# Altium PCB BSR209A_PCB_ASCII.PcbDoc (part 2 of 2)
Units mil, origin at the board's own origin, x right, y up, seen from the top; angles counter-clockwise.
Board outline 3820.03 x 2030.03 mil, 4 copper layers (Top Layer, MidLayer1, MidLayer2, Bottom Layer), stack 59.4 mil thick; 68 components, 18 nets, 122 pads, 73 vias.
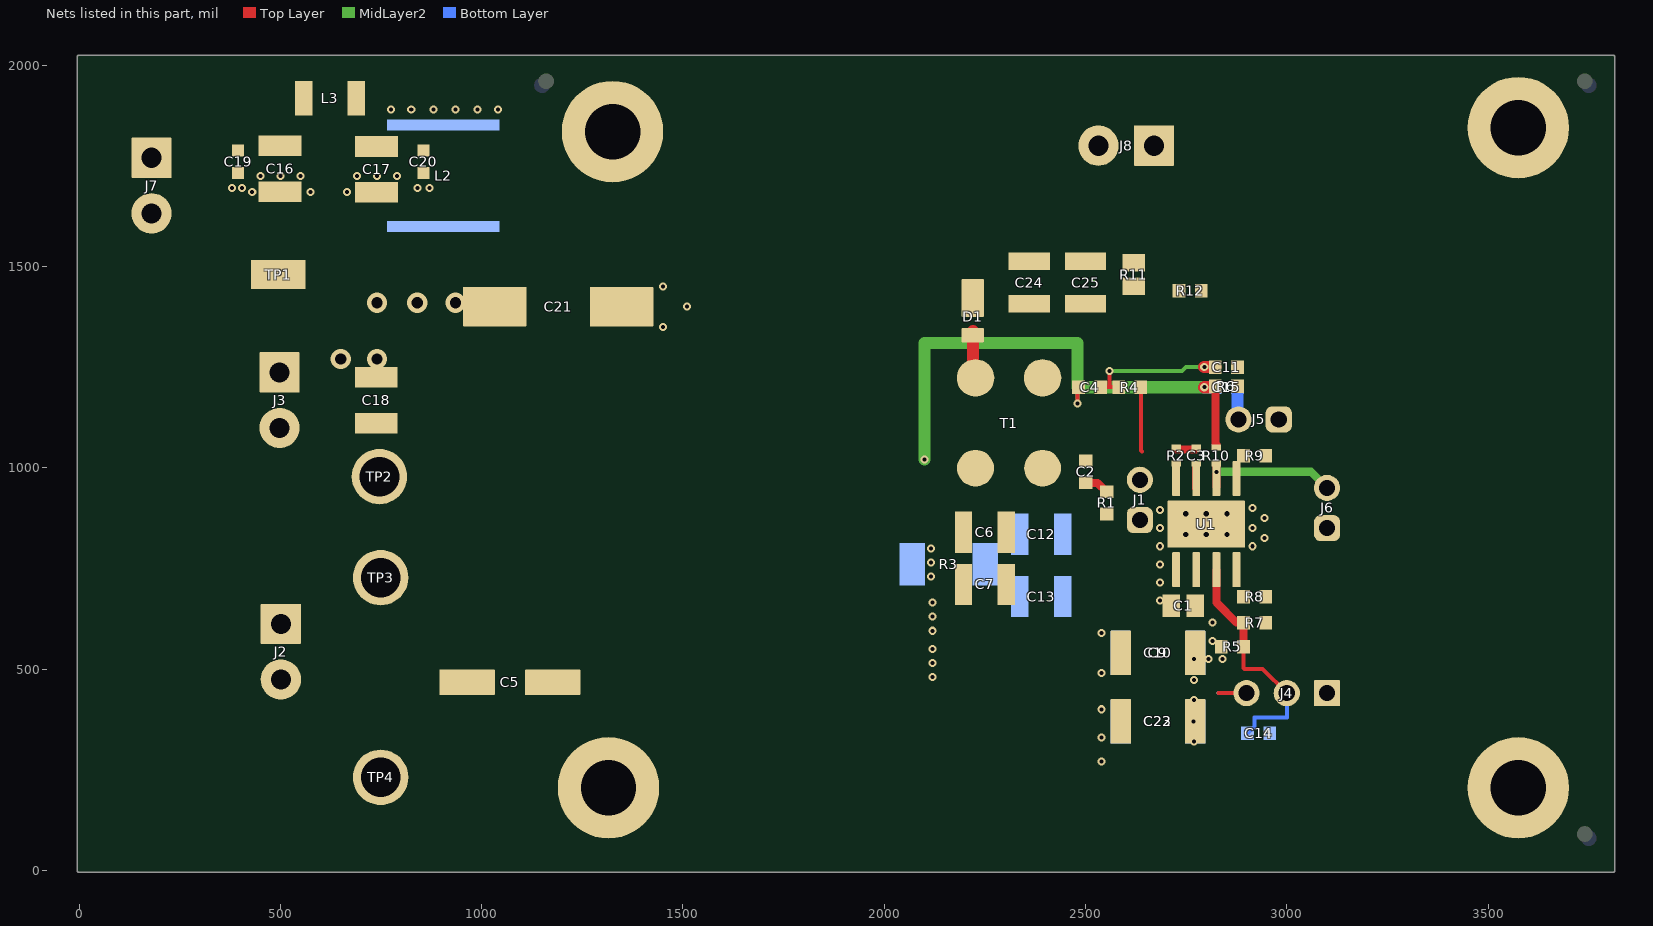
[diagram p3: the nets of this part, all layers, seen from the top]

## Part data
C1: library part CMP-0007897-1, "CAP, CERM, 0.1 uF, 250 V, +/- 10%, X7T, 0805"
C2: library part CMP-0081318-1, "CAP, CERM, 1000 pF, 200 V,+/- 10%, X7R, 0603"
C3: library part CMP-0006357-2, "CAP, CERM, 2200 pF, 50 V, +/- 10%, X7R, AEC-Q200 Grade 1, 0402"
C4: library part CMP-0007087-4, "CAP, CERM, 3300 pF, 100 V, +/- 10%, X7R, AEC-Q200 Grade 1, 0603"
C5: library part CMP-0081462-1, "CAP, AL, 100 µF, 25 V, +/- 20%, SMD"
C6 C7 C24 C25: library part CMP-0084059-1, "CAP, CERM, 22 µF, 25 V,+/- 10%, X5R, AEC-Q200 Grade 3, 1210"
C9 C10 C22 C23: library part CMP-0091301-1, "Cap Ceramic 1uF 250V X7T 10% Pad SMD 1812 +125°C Automotive T/R"
C11: library part CMP-0006952-4, "CAP, CERM, 56 pF, 50 V, +/- 5%, C0G/NP0, 0603"
C12 C13: library part CMP-0009255-2, "CAP, CERM, 22 uF, 25 V, +/- 10%, X7R, AEC-Q200 Grade 1, 1210"
C14: library part CMP-0080063-1, "CAP, CERM, 0.01 µF, 100 V,+/- 10%, X8R, AEC-Q200 Grade 0, 0603"
C15: library part CMP-0006844-4, "CAP, CERM, 1000 pF, 50 V, +/- 5%, X7R, AEC-Q200 Grade 1, 0603"
C16 C17 C18: library part CMP-0009150-2, "CAP, CERM, 4.7 uF, 100 V, +/- 10%, X7S, AEC-Q200 Grade 1, 1210"
C19 C20: library part CMP-0081011-1, "CAP, CERM, 0.1 µF, 100 V,+/- 10%, X7R, AEC-Q200 Grade 1, 0603"
C21: library part CMP-0091226-1, "Aluminum Electrolytic Capacitors Radial 33uF 20% 160V, Can - SMD - 2000 Hrs @ 125°C"
D1: library part CMP-0093179-1, "Rectifier Diode Schottky 200V 1A 2-Pin SOD-123HE T/R"
FID1 FID2 FID3 FID4 FID5 FID6: library part CMP-0077181-1, "Fiducial mark.  There is nothing to buy or mount."
J1 J5 J6: library part CMP-0075405-2, "Header, 100mil, 2x1, Gold, TH"
J2 J3 J7 J8: library part CMP-0074913-1, "Terminal Block, 3.5mm Pitch, 2x1, TH"
J4: library part CMP-0075484-1, "Header, 100mil, 3x1, Gold, TH"
L2: library part CMP-0061601-2, "Inductor, Shielded Drum Core, Ferrite, 15 uH, 1.8 A, 0.05 ohm, AEC-Q200 Grade 1, SMD"
L3: library part CMP-0003373-1, "Ferrite Bead, 2000 ohm @ 100 MHz, 1.2 A, 1210"
Logo1: library part CMP-0074838-1, "Texas Instrument Corporate Signature"
Logo2: library part CMP-0074844-1
Logo3: library part CMP-0074847-1, "FCC_disclaimer"
Logo4: library part CMP-0074769-1
Logo5: library part IEC_HighVoltage, "IEC 61010-1 High Voltage Warning"
Logo6: library part IEC_HotSurface, "IEC 61010-1 Hot Surface Warning"
R1: library part CMP-0025743-4, "RES, 1.0, 5%, 0.1 W, AEC-Q200 Grade 0, 0603"
R2: library part CMP-0026822-3, "RES, 0, 5%, 0.063 W, AEC-Q200 Grade 0, 0402"
R3: library part CMP-0016525-2, "RES, 0.2, 1%, 1 W, 2010"
R4: library part CMP-0022758-4, "RES, 118 k, 1%, 0.1 W, 0603"
R5: library part CMP-0022899-4, "RES, 1.00 M, 1%, 0.1 W, 0603"
R6: library part CMP-0023120-4, "RES, 453 k, 1%, 0.1 W, 0603"
R7: library part CMP-0023034-4, "RES, 332 k, 1%, 0.1 W, 0603"
R8: library part CMP-0023036-5, "RES, 33.2 k, 1%, 0.1 W, 0603"
R9: library part CMP-0023216-5, "RES, 61.9 k, 1%, 0.1 W, 0603"
R10: library part CMP-0026659-1, "RES, 100 k, 1%, 0.1 W, 0402"
R11: library part CMP-0020951-3, "RES, 1.00 k, 1%, 0.125 W, AEC-Q200 Grade 0, 0805"
R12: library part CMP-0025697-4, "RES, 0, 5%, 0.1 W, AEC-Q200 Grade 0, 0603"
T1: library part CMP-0091289-1, "Power inductor, coupled, shielded, 20% tol, RoHS, halogen-free"
TP1: library part CMP-0075188-1, "Test Lead clips and hooks, SMT"
TP2 TP3 TP4: library part 1598-2, "Terminal, Turret, TH, Triple"
U1: library part CMP-0092717-1, "0.3-A, 120-V, Step-Down Converter with Fly-buck Capability, HSOIC8"
ZZ2: library part CMP-0077236-1
ZZ3: library part CMP-0077237-1
ZZ4: library part CMP-0077238-1

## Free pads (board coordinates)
  round 251.97 hole 137.8: 1(1315,205) 1(1325,1835) 1(3575,205) 1(3575,1845)

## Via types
v1: diameter 20, hole 10, Top Layer to Bottom Layer, tented both sides, 62 vias
v2: diameter 24.8, hole 12.99, Top Layer to Bottom Layer, 6 vias
v3: diameter 50, hole 28, Top Layer to Bottom Layer, tented both sides, 5 vias

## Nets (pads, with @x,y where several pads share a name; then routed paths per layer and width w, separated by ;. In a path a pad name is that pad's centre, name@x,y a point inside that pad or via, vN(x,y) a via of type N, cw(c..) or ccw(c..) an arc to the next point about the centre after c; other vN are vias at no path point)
BST: C3.2 U1.7 | length 52.4
  Top Layer w20: U1.7@2775,950 U1.7@2775,1002.44
EN: C14.1 J4.2 R5.1 R7.2 U1.3 | length 603
  Top Layer w10: R5.1@2892.56,555 2892.56,502.44 2895,500 2940,500 J4.2@3000,440
  Top Layer w20: U1.3@2825,746.65 2825,665 2875,615 R7.2@2892.44,615 2892.56,614.88 R5.1@2892.56,555
  Bottom Layer w10: C14.1@2902.44,340 2920,357.56 2920,380 3000,380 J4.2@3000,440
FB: C11.2 C15.2 J5.2 R6.1 R9.2 U1.5 | length 76
  Bottom Layer w30: C15.2@2877.56,1200 2877.56,1127.44 J5.2@2880,1125
GND: C1.2 C5.2 C6.2 C7.2 C9.1 C10.1 C12.2 C13.2 C14.2 C16.2 C17.2 C18.2 C19.2 C20.2 C21.1 C22.1 C23.1 J1.1 J2.1 J3.2 J4.1 J5.1 J6.1 J7.2 pad.1 R1.1 R7.1 R8.1 R9.1 R12.2 TP2.1 TP3.1 U1.1 U1.9
  other v1: 2540,270 2540,330 2540,400 2540,490 2539.61,590 2685,670 2685,715 2685,760 2685,805 2915,805 2945,825 2685,850 2915,850 2945,875 2685,895 2915,900 1450,1350 1510,1400 1450,1450 430,1685 575,1685 665,1685 380,1695 405,1695 840,1695 870.26,1695 450,1725 500,1725 550,1725 690,1725 740,1725 790,1725
  other v2: 2748.82,834.41 2800,834.41 2851.18,834.41 2748.82,885.59 2800,885.59 2851.18,885.59
GND2: C24.2 C25.2 J8.1 R11.1 R12.1 T1.1
NetC2_1: C2.1 R1.2 | length 61.3
  Top Layer w20: C2.1@2500,962.44 2530.12,962.44 R1.2@2552.2,940.36
NetC3_1: C3.1 R2.1 | length 50
  Top Layer w20: R2.1@2725,1045 C3.1@2775,1045
NetC4_2: C4.2 C11.1 R4.2 | length 351.5
  Top Layer w10: C4.2@2537.56,1200 2560,1200 ; v1(2560,1240) 2560,1200 ; R4.2@2582.44,1200 2560,1200
  Top Layer w30: v1(2795,1250) C11.1@2822.44,1250
  MidLayer2 w10: v1(2560,1240) 2740,1240 2750,1250 v1(2795,1250)
NetC12_1: C12.1 C13.1 R3.1
NetC16_1: C16.1 C19.1 J7.1 L3.1
NetC17_1: C17.1 C20.1 L2.1 L3.2
  other v1: 775,1890 825,1890 880,1890 935,1890 990,1890 1040,1890
PG: J6.2 R10.1 U1.6 | length 340.7
  Top Layer w20: U1.6@2825,953.35 v1(2825,990) U1.6@2825,1002.44
  MidLayer2 w20: v1(2825,990) 3060,990 J6.2@3100,950
RON: R8.2 U1.4
S1: D1.2 T1.2 | length 119.4
  Top Layer w10: T1.2@2220,1229.92 T1.2@2226.73,1223.19
  Top Layer w30: T1.2@2220,1229.92 D1.2@2220,1339.8
SW: C2.2 J1.2 R2.2 R4.1 T1.4 U1.8 | length 161
  Top Layer w10: R4.1@2637.56,1200 2637.56,1042.44 2640,1040
VIN: C1.1 C9.2 C10.2 C18.1 C21.2 C22.2 C23.2 J3.1 J4.3 L2.2 R5.2 TP1.1 U1.2 | length 140
  Top Layer w10: 2830,440 J4.3@2900,440
  Bottom Layer w10: 2830,440 J4.3@2900,440
  other v1: 2770,320 2768.74,370 2770,423.07 2770,473.07 2770,525 2805,525 2840,525 2815,570 2815,615
  other v3: 650,1270 740,1270 740,1410 840,1410 934.7,1410
VOUT: C4.1 C5.1 C6.1 C7.1 C15.1 J2.2 R3.2 R6.2 R10.2 T1.3 TP4.1 | length 1378
  Top Layer w10: v1(2480,1160) 2480,1197.56 C4.1@2482.44,1200
  Top Layer w18: R6.2@2822.44,1200 R6.2@2825,1197.44
  Top Layer w20: R6.2@2822.44,1200 2822.44,1060.12 2825,1057.56
  Top Layer w30: v1(2795,1200) R6.2@2822.44,1200
  MidLayer2 w10: v1(2480,1160) 2480,1200
  MidLayer2 w30: v1(2100,1020) 2100,1310 2480,1310 2480,1200 v1(2795,1200)
  Bottom Layer w30: v1(2795,1200) C15.1@2822.44,1200
  other v1: 2120,480 2120,515 2120,550 2120,595 2120,630 2120,665 2116.08,729.42 2116.08,764.42 2116.08,799.42
VOUT2: C24.1 C25.1 D1.1 J8.2 R11.2
pads on no net: FID1.1 FID2.1 FID3.1 FID4.1 FID5.1 FID6.1

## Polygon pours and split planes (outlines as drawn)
GND on MidLayer1 "GND_L02_P289" (solid, remove dead copper, pour order 289): 1095,1750 605,1750 605,1445 640,1410 1095,1410
GND on MidLayer1 "GND_L02_P269" (solid, remove dead copper, pour order 269): 67.45,1453 1102,1453 1102,0 69.99,0
GND on MidLayer1 "GND_L02_P227" (solid, pour order 227): 3810,2020 3810,0 1084,0 1084,2020
VIN on Top Layer "VIN_L01_P291" (solid, remove dead copper, pour order 291): 2740,600 2840,600 2840,300 2740,300
NetC17_1 on Top Layer "NETC17_1_L01_P281" (solid, remove dead copper, pour order 281): 645,1970 645,1770 1060,1770 1060,1970
FB on Top Layer "FB_L01_P217" (solid, remove dead copper, pour order 217): 2855,928.19 2910,928.19 2910,1160 2855,1160
GND on Top Layer "GND_L01_P273" (solid, remove dead copper, pour order 273): 340,1743 900,1743 900,1657 340,1657
NetC16_1 on Top Layer "NETC16_1_L01_P235" (solid, remove dead copper, pour order 235): 0.01,1968 0.01,1769 587,1769 587,1968
NetC16_1 on Top Layer "NETC16_1_L01_P275" (solid, remove dead copper, pour order 275): 0,1918 0,1658 316.5,1658 316.5,1918
RON on Top Layer "RON_L01_P234" (solid, pour order 234): 2864.41,665 2910,665 2910,770 2864.41,770
VIN on Top Layer "VIN_L01_P225" (solid, remove dead copper, pour order 225): 2757.17,770.65 2852.2,770.65 2852.2,515 2757.17,515
GND on Top Layer "GND_L01_P228" (solid, remove dead copper, pour order 228): 0,1136 0,569 1223,569 1223,1136
VIN on Top Layer "VIN_L01_P229" (solid, remove dead copper, pour order 229): 334,1605 334,1192 1064,1192 1064,1605
VOUT on Top Layer "VOUT_L01_P230" (solid, remove dead copper, pour order 230): 315,511 315,102 1061,102 1061,511
SW on Top Layer "SW_L01_P233" (solid, pour order 233): 2340,928.65 2340,1055 2740,1055 2740,928.65
VOUT on Top Layer "VOUT_L01_P221" (solid, remove dead copper, pour order 221): 2060.83,1050.26 2265.75,1050.26 2265.75,450 2061.11,450
FB on Top Layer "FB_L01_P216" (solid, remove dead copper, pour order 216): 2855,1121.73 2908.58,1121.73 2908.58,1265 2855,1265
VOUT2 on Top Layer "VOUT2_L01_P307" (solid, remove dead copper, pour order 307): 2170,1550 2660,1550 2660,1480 2640,1460 2280,1460 2280,1400 2170,1400
GND2 on Top Layer "GND2_L01_P309" (solid, remove dead copper, pour order 309): 2304.88,1440 2740,1440 2740,1330 2300,1330 2300,1435.12
VOUT2 on Top Layer "VOUT2_L01_P311" (solid, remove dead copper, pour order 311): 2446.85,1866.88 2570,1866.88 2570,1496.88 2562.76,1504.12 2446.85,1504.12 2446.85,1835.03
GND2 on Top Layer "GND2_L01_P315" (solid, remove dead copper, pour order 315): 2450,1870 2740,1870 2740,1730 2730,1720 2450,1720
GND2 on Top Layer "GND2_L01_P321" (solid, remove dead copper, pour order 321): 2340,1340 2440,1340 2440,1269.92 2437.56,1267.48 2340,1267.48
GND on Top Layer "GND_L01_P323" (solid, remove dead copper, pour order 323): 3799.72,2009.72 3799.72,10.28 1070,10.28 1070,2010
GND on Bottom Layer "GND_L04_P297" (solid, remove dead copper, pour order 297): 1090,2000 3790,2000 3790,20 1090,20
VIN on Bottom Layer "VIN_L04_P295" (solid, remove dead copper, pour order 295): 2754.66,536.3 2843.35,536.3 2843.35,233.35 2840,230 2829.92,240.08 2750,240.08 2750,531.64
NetC17_1 on Bottom Layer "NETC17_1_L04_P287" (solid, remove dead copper, pour order 287): 1060,1910 1060,1760 755.39,1760 755.39,1905.39 760,1910
VIN on Bottom Layer "VIN_L04_P285" (solid, remove dead copper, pour order 285): 1054.61,1685 695,1685 695,1360 1055,1360
GND on Bottom Layer "GND_L04_P283" (solid, remove dead copper, pour order 283): 10,1915 10,1660 610,1660 610,1915
VIN on Bottom Layer "VIN_L04_P208" (solid, remove dead copper, pour order 208): 2853.53,510.84 2852.69,510 2750,510 2750,650 2825,650 2825,550 2855,550
NetC12_1 on Bottom Layer "NETC12_1_L04_P209" (solid, remove dead copper, pour order 209): 2192.22,830 2297.22,830 2297.22,920 2377.22,920 2377.22,615 2297.22,615 2297.22,710 2192.22,710
GND on Bottom Layer "GND_L04_P231" (solid, remove dead copper, pour order 231): 334,1166 334,0 1245.45,0 1241.36,1166
GND on MidLayer2 "GND_L03_P301" (solid, remove dead copper, pour order 301): 1040,2020 3800,2020 3800,10 3790,0 1040,0
VIN on MidLayer2 "VIN_L03_P299" (solid, remove dead copper, pour order 299): 2710,510 2820.08,510 2820.08,290.08 2820,290 2710,290
GND on MidLayer2 "GND_L03_P271" (solid, remove dead copper, pour order 271): 1421.96,815 341,815 341,1 1423.59,1
VIN on MidLayer2 "VIN_L03_P236" (solid, remove dead copper, pour order 236): 1687.27,1565 2072.27,1180 2285,1180 2860,605 2860,494.61 2399.86,494.61 2024.73,805 345,805 345,1565
VOUT on MidLayer2 "VOUT_L03_P211" (solid, remove dead copper, pour order 211): 2165,650 2165,470 2045,350 1145,350 1085,100 445,110 445,782.5 2005,782.5

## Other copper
Top Layer:
  rectangle net GND: 10,1110 320,1640
  rectangle net VOUT: 2070,930 2280,1050
  rectangle net GND2: 2670,1330 2740,1850
  text ".Layer_Name" at -751,-1769.49 h60
Bottom Layer:
  rectangle net VOUT: 2060,702.91 2140,817.09
  text ".Layer_Name" at -751,-1769.49 h60

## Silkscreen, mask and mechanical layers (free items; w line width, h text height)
Top Overlay:
  lines w10: 2683.04,781.24 ccw(c2674.09,776.77) 2684.09,776.77
  text "+" at 150,1870 h100
  text "+" at 2370,1770 h100
  text "10V" at 2790,1710 h72.83
  text "6V - 115V" at 110,1300 h72.83 r270
  text "+" at 250,1210 h100
  text "10V" at 110,580 h72.83 r270
  text "LM5168FEVM - BSR209A" at 3720,470 h130 r90
  text "+" at 250,420 h100
  text "ON" at 2848.35,301.3 h72.83
  text "OFF" at 3050,300 h72.83
  text "DANGER HIGH VOLTAGE" at 1510,130 h40
  text ".Layer_Name" at -751,-1769.49 h60
Bottom Overlay:
  text ".Layer_Name" at -751,-1769.49 h60
Top Paste:
  text ".Layer_Name" at -751,-1769.49 h60
Bottom Paste:
  text ".Layer_Name" at -751,-1769.49 h60
Top Solder:
  text ".Layer_Name" at -751,-1769.49 h60
  text ".Layer_Name" at -751,-1769.49 h60
Bottom Solder:
  text ".Layer_Name" at -751,-1769.49 h60
Drill Guide:
  text ".Layer_Name" at -751,-1769.49 h60
M1 Board Outline:
  lines w10: -10,0 -10,2010 0,2020 ; 315,0 0,0 ; 318,0 3810,0 ; 0,0 3810,0 ; 0,0 0,2020 ; 0,2020 3810,2020 ; 0,2020 315,2020 3810,2020 ; 3810,0 3810,2020 ; 3810,0 3810,2020
  text ".Layer_Name" at -751,-1769.49 h60
M2 Board Dimensions:
  rectangle: -1328,-1196.5 -1203,-1071.5
  rectangle: -1203,-1321.5 -828,-1196.5
  lines w7: -1328,-1196.5 -328,-1196.5 ; -1203,-1321.5 -1203,-1071.5 ; -1078,-1321.5 -1078,-1071.5 ; -828,-1321.5 -828,-1071.5 ; -578,-1321.5 -578,-1071.5 ; -1328,-1321.5 -328,-1321.5 -328,-1071.5 -1328,-1071.5 -1328,-1321.5
  text ".Layer_Name" at -751,-1769.49 h60
M3 3D STEP Top:
  text ".Layer_Name" at -751,-1769.49 h60
M4 3D STEP Bottom:
  text ".Layer_Name" at -751,-1769.49 h60
M5 Assembly Top:
  lines w10: -1620,-1841.17 4980,-1841.17 ; -1620,-1637.83 4982,-1637.83 ; -1620,-1434.5 -1620,-2044.5 2385,-2044.5 4982,-2044.5 4982,-1434.5 -1619.5,-1434.5 -1619.5,-2044.5 -44,-2044.5 ; 845,-2044.5 845,-1434.5 ; 2112,-1637.83 2112,-1434.5 ; 2952,-1637.83 2952,-1434.5 ; 3574,-2051 3574,-1848.17
  text "COMPONENTS MARKED 'DNP' SHOULD NOT BE POPULATED." at -174.5,-1229.5 h60
  text "ASSEMBLY VARIANT:" at -175,-1345 h60
  text ".VariantName" at 861,-1345 h60
  text "PCB VIEWED FROM TOP SIDE" at -1556.5,-1566.67 h60
  text "BOARD #:" at 920,-1566.67 h60
  text ".PRJ_Number" at 1465.5,-1566.67 h60
  text "REV:" at 2310,-1566.67 h60
  text ".PCB_Rev" at 2601.5,-1566.67 h60
  text "SVN REV:" at 3148,-1566.67 h60
  text ".VersionControl_RevNumber" at 3654,-1566.67 h60
  text "IGNORE ->" at -1556.5,-1769.49 h60
  text "PLOT NAME =" at -1556.5,-1975.34 h60
  text ".plot_File_Name" at -751,-1975.34 h60
  text "GENERATED    :" at 922,-1975.34 h60
  text ".Print_Date" at 1791.5,-1975.34 h60
  text ".Print_Time" at 2520.5,-1975.34 h60
  text "TEXAS INSTRUMENTS" at 3785,-1975.34 h60
M6 Assembly Bottom:
  lines w10: -1620.5,-1638.33 4981.5,-1638.33 ; -1618.5,-1841.67 4981.5,-1841.67 ; -212.5,-2051.5 -212.5,-1848.67 ; 409.5,-1638.33 409.5,-1435 ; 1249.5,-1638.33 1249.5,-1435 ; 2516.5,-2045 2516.5,-1435 ; 3405.5,-2045 4981,-2045 4981,-1435 -1620.5,-1435 -1620.5,-2045 976.5,-2045 4981.5,-2045 4981.5,-1435
  text "COMPONENTS MARKED 'DNP' SHOULD NOT BE POPULATED." at 4774,-1229 h60
  text ".VariantName" at 3730,-1345 h60
  text "ASSEMBLY VARIANT:" at 4769,-1345 h60
  text ".VersionControl_RevNumber" at -292.5,-1567.17 h60
  text "SVN REV:" at 213.5,-1567.17 h60
  text ".PCB_Rev" at 760,-1567.17 h60
  text "REV:" at 1051.5,-1567.17 h60
  text ".PRJ_Number" at 1896,-1567.17 h60
  text "BOARD #:" at 2441.5,-1567.17 h60
  text "PCB VIEWED FROM BOTTOM SIDE" at 4918,-1567.17 h60
  text "IGNORE ->" at 1219.85,-1769.49 h60
  text "TEXAS INSTRUMENTS" at -423.5,-1975.84 h60
  text ".Print_Time" at 841,-1975.84 h60
  text ".Print_Date" at 1570,-1975.84 h60
  text "GENERATED    :" at 2439.5,-1975.84 h60
  text ".plot_File_Name" at 4112.5,-1975.84 h60
  text "PLOT NAME =" at 4918,-1975.84 h60
M9 Title Sheet:
  lines w10: -1819.5,130.5 -1619.5,130.5 ; -1819.5,2505.5 -1619.5,2505.5 ; -1819.5,4880.5 -1619.5,4880.5 ; 680.5,-2244.5 680.5,-2044.5 ; 680.5,7055.5 680.5,7255.5 ; 3180.5,-2244.5 3180.5,-2044.5 ; 3180.5,7055.5 3180.5,7255.5 ; 4993,-2044.5 4993,-1434.5 9975.5,-1434.5 ; 5680.5,-2244.5 5680.5,-2044.5 ; 5680.5,7055.5 5680.5,7255.5 ; 8180.5,-2244.5 8180.5,-2044.5 ; 8180.5,7055.5 8180.5,7255.5 ; 9975.5,-2044.5 9975.5,-1434.5 ; 9975.5,-1734.5 12975.5,-1734.5 ; 9975.5,-1134.5 12975.5,-1134.5 ; 9976.5,-540.5 12976.5,-540.5 ; 10680.5,-2244.5 10680.5,-2044.5 ; 10680.5,7055.5 10680.5,7255.5 ; 11480.5,-2034.5 11480.5,-1434.5 ; 12975.5,-1434.5 9975.5,-1434.5 ; 12975.5,-834.5 9975.5,-834.5 ; 12980.5,-844.5 12980.5,-2044.5 ; 12980.5,-40 9976.5,-40 9975.5,-40 9975.5,-540.5 9975.5,-834.5 ; 12980.5,130.5 13180.5,130.5 ; 12980.5,2505.5 13180.5,2505.5 ; 12980.5,4880.5 13180.5,4880.5 ; 9975.5,-1434.5 9975.5,-834.5 ; 12980.5,-2044.5 12980.5,7055.5 -1619.5,7055.5 -1619.5,-2044.5 12980.5,-2044.5 ; -1819.5,-2244.5 -1819.5,7255.5 13180.5,7255.5 13180.5,-2244.5 -1819.5,-2244.5
  text "1" at -588.16,7125.5 h70
  text "2" at 1907.5,7125.5 h70
  text "3" at 4396.84,7125.5 h70
  text "4" at 6903.51,7125.5 h70
  text "5" at 9402.5,7125.5 h70
  text "6" at 11907.5,7125.5 h70
  text "A" at -1744.5,5982.5 h70
  text "A" at 13055.5,5982.5 h70
  text "B" at -1744.5,3602.5 h70
  text "B" at 13055.5,3602.5 h70
  text "C" at -1744.5,1227.5 h70
  text "C" at 13055.5,1227.5 h70
  text "PROJECT TITLE:" at 10015.5,-633.5 h45
  text "BSR041" at 10065.5,-766.83 h70
  text "DESIGNED FOR:" at 10015.5,-934.5 h45
  text "D" at -1744.5,-1142.5 h70
  text "D" at 13055.5,-1142.5 h70
  text "FILE NAME:" at 10015.5,-1234.5 h45
  text "Texas Instruments (TI) and/or its licensors do not warrant the accuracy or completeness of this specification" at 5046,-1516.34 h45
  text "ENGINEER:" at 10015.5,-1524.5 h45
  text "LAYOUT BY:" at 11520.5,-1524.5 h45
  text "or any information contained therein. TI and/or its licensors do not warrant that this design will meet" at 5001.01,-1629 h45
  text "Brani Dubocanin" at 10065.5,-1679.49 h70
  text "Robert Loke" at 11571,-1679.49 h70
  text "the specifications, will be suitable for your application or fit for any particular purpose, or will operate in" at 5001.01,-1741.67 h45
  text ".Layer_Name" at -751,-1769.49 h60
  text "ALTIUM DESIGNER VERSION:" at 11520.5,-1834.5 h45
  text "an implementation. TI and/or its licensors do not warrant that the design is production worthy. You should" at 5001.01,-1854.33 h45
  text "completely validate and test your design implementation to confirm the system functionality for your application." at 5046,-1967 h45
  text ".print_Scale" at 10065.5,-1967.83 h70
  text ".Application_BuildNumber" at 11571,-1967.83 h70
  text "1" at -588.16,-2174.5 h70
  text "2" at 1907.5,-2174.5 h70
  text "3" at 4396.84,-2174.5 h70
  text "4" at 6903.51,-2174.5 h70
  text "5" at 9402.5,-2174.5 h70
  text "6" at 11907.5,-2174.5 h70
M10 Fab Notes:
  drawing of 185 lines, arcs and shapes, not listed
  text "DESIGN INFORMATION" at 11053.02,4999 h60
  text "MIN. TRACK WIDTH:" at 10408.46,4819 h60
  text "8" at 11504.7,4819 h60
  text "MIL" at 11659.46,4819 h60
  text "MIN. CLEARANCE:" at 10408.46,4687 h60
  text "MIL" at 11659.46,4687 h60
  text "10" at 11478,4686 h60
  text "MIN. VIA PAD SIZE:" at 10408.46,4555 h60
  text "24" at 11474.71,4555 h60
  text "MIL" at 11659.46,4555 h60
  text "0.05mm (2MIL)" at 11103.46,4413.29 h60
  text "MINIMUM ANNULAR RING" at 10079.23,4409 h60
  text "EXTERNAL" at 11811.46,4409 h60
  text "PER" at 10279.23,4291 h60
  text "IPC-D-275 CLASS 2 LEVEL C" at 10499.23,4291 h60
  text "MIL, HOLES" at 11987.46,4178.71 h60
  text "+/-" at 11595,4178 h60
  text "+/-" at 12449,4178 h60
  text "REGISTRATION TOLERANCES:" at 10079.23,4173 h60
  text "METAL" at 11279,4173 h60
  text "5" at 11855.2,4173 h60
  text "3" at 12688.2,4173 h60
  text "MIL" at 12804.46,4173 h60
  text "MATERIAL:" at 10004.46,3963.54 h60
  text "FR-4 High Tg" at 10990.9,3823.21 h60
  text "FR-408" at 10425.46,3814.64 h60
  text "X" at 10837.46,3814.64 h60
  text "OTHER" at 11913.46,3814.64 h60
  text "62 MIL (1.6mm) +/-10%" at 10745.56,3651.92 h60
  text "THICKNESS:" at 10079.23,3647.64 h60
  text "X" at 10617.4,3647.64 h60
  text "OTHER" at 12030.46,3647.64 h60
  text "TOLERANCE:" at 10079.23,3489.64 h60
  text "X" at 10918.53,3489.64 h60
  text "ANSI IPC-6012 TYPE 3 CLASS 2" at 11105.48,3489.64 h60
  text "OTHER +/-" at 11105.46,3333.64 h60
  text "BOW & TWIST:" at 10079.23,3176.64 h60
  text "X" at 10918.53,3176.64 h60
  text "ANSI IPC-6012 TYPE 3 CLASS 2" at 11105.48,3176.64 h60
  text "OTHER +/-" at 11105.46,3018.13 h60
  text "DRILLING:" at 10004.46,2879.64 h60
  text "REFERENCE:" at 10079.23,2762.64 h60
  text "X" at 10727.46,2762.64 h60
  text "AS SHOWN" at 10914.46,2762.64 h60
  text "X" at 11628.46,2762.64 h60
  text "NC_DRILL FILES" at 11765.46,2762.64 h60
  text "PTH MIN COPPER THICKNESS:" at 10079.23,2604.64 h60
  text "X" at 11429.46,2604.64 h60
  text "1MIL" at 11566.46,2604.64 h60
  text "OTHER" at 12063.46,2604.64 h60
  text "BOARD FINISH:" at 10004.46,2445.64 h60
  text "SILKSCREEN:" at 10159.68,2327.64 h60
  text "X" at 11108.46,2327.64 h60
  text "TOP" at 11234.46,2327.64 h60
  text "X" at 11618.46,2327.64 h60
  text "BOTTOM" at 11745.46,2327.64 h60
  text "SILKSCREEN COLOR:" at 10159.68,2160.64 h60
  text "X" at 11107.42,2160.64 h60
  text "WHITE" at 11234.46,2160.64 h60
  text "OTHER" at 11745.46,2160.64 h60
  text "SOLDER RESIST COLOR:" at 10159.68,1990.64 h60
  text "X" at 10727.42,1831.44 h60
  text "GREEN" at 10854.46,1831.44 h60
  text "BLUE" at 11445.46,1831.44 h60
  text "OTHER" at 11983.46,1831.44 h60
  text "IMMERSION GOLD (ENIG)" at 11065.46,1642.92 h60
  text "ENEPIG" at 12403,1639.64 h60
  text "SURFACE FINISH:" at 10004.46,1638.64 h60
  text "X" at 10878.51,1638.64 h60
  text "IMM. TIN/SILVER OR EQUIV" at 10334,1481.64 h60
  text "OTHER" at 11765.46,1481.64 h60
  text "ARRAY/PANEL:" at 10004.46,1302.64 h60
  text "CUT AND TRIM PER MECH LAYER 1" at 11065.46,1298.35 h60
  text "N.C. ROUTE" at 11065.46,1146.64 h60
  text "V. SCORE" at 11931.46,1146.64 h60
  text "CERTIFICATION:" at 10004.46,1009.64 h60
  text "MATERIALS AND WORKMANSHIP FOR ALL PCBS" at 10729.46,1009.64 h60
  text "TO MEET OR EXCEED THE REQUIREMENTS OF:" at 10729.46,911.64 h60
  text "X" at 10355.96,775.13 h60
  text "ANSI IPC-A-600F CLASS ->" at 10494.96,775.13 h60
  text "X" at 12134.02,775.13 h60
  text "2" at 12252.96,775.14 h60
  text "1" at 11937.96,773.64 h60
  text "3" at 12606.96,773.64 h60
  text "X" at 10358.02,615.64 h60
  text "UL 94V-0" at 10494.96,615.64 h60
  text "X" at 11170.02,615.64 h60
  text "RoHS" at 11306.96,615.64 h60
  text "OTHER" at 11951.36,615.64 h60
  text "PER ORDER" at 12348.42,615.64 h60
  text "ADDITIONAL REQUIREMENTS:" at 10004.46,474.64 h60
  text "MICROSECTION:" at 10079.23,359.64 h60
  text "YES" at 10984.96,359.64 h60
  text "X" at 11267,205 h60
  text "REQUIRED" at 11846.46,203.49 h60
  text "BARE BOARD ELEC. TEST:" at 10079.23,200.64 h60
  text "NONE" at 11384.96,200.64 h60
  text "PER ORDER" at 12438.46,200.64 h60
  text "MANUFACTURER'S UL:" at 10079.23,43.64 h60
  text "RAIL" at 11244.96,39.35 h60
  text "METAL" at 11736.77,39.35 h60
  text "X" at 12112,39 h60
  text "SILK" at 12248.46,39.35 h60
  text ".Layer_Name" at -751,-1769.49 h60
M11 Gerber Information:
  lines w10: -1620,-1841.17 4980,-1841.17 ; -1620,-1637.83 4982,-1637.83 ; -1620,-1434.5 -1620,-2044.5 2385,-2044.5 4982,-2044.5 4982,-1434.5 -1619.5,-1434.5 -1619.5,-2044.5 -44,-2044.5 ; 845,-2044.5 845,-1434.5 ; 2112,-1637.83 2112,-1434.5 ; 2952,-1637.83 2952,-1434.5 ; 3574,-2051 3574,-1848.17
  text "ALL ARTWORK VIEWED FROM TOP SIDE" at -1556.5,-1566.67 h60
  text "BOARD #:" at 920,-1566.67 h60
  text ".PRJ_Number" at 1465.5,-1566.67 h60
  text "REV:" at 2310,-1566.67 h60
  text ".PCB_Rev" at 2601.5,-1566.67 h60
  text "SVN REV:" at 3148,-1566.67 h60
  text ".VersionControl_RevNumber" at 3654,-1566.67 h60
  text "LAYER NAME =" at -1556.5,-1769.49 h60
  text "PLOT NAME =" at -1556.5,-1975.34 h60
  text ".plot_File_Name" at -751,-1975.34 h60
  text "GENERATED    :" at 922,-1975.34 h60
  text ".Print_Date" at 1791.5,-1975.34 h60
  text ".Print_Time" at 2520.5,-1975.34 h60
  text "TEXAS INSTRUMENTS" at 3785,-1975.34 h60
M12 Stackup:
  drawing of 295 lines, arcs and shapes, not listed
  text "Layer" at 2740.09,6380 h60
  text "Name" at 3150,6380 h60
  text "Material" at 4079.74,6380 h60
  text "Thickness" at 4939.51,6380 h60
  text "Constant" at 5589.35,6380 h60
  text "Board Layer Stack" at 6159.21,6380 h60
  text "1" at 2740.09,6260 h60
  text "Top Overlay" at 3150,6260 h60
  text "2" at 2740.09,6140 h60
  text "Top Solder" at 3150,6140 h60
  text "Solder Resist" at 4079.74,6140 h60
  text "0.40mil" at 4939.51,6140 h60
  text "3.5" at 5589.35,6140 h60
  text "3" at 2740.09,6020 h60
  text "Top Layer" at 3150,6020 h60
  text "Copper" at 4079.74,6020 h60
  text "2.80mil" at 4939.51,6020 h60
  text "4" at 2740.09,5900 h60
  text "Dielectric1" at 3150,5900 h60
  text "FR-4" at 4079.74,5900 h60
  text "10.00mil" at 4939.51,5900 h60
  text "4.8" at 5589.35,5900 h60
  text "5" at 2740.09,5780 h60
  text "MidLayer1" at 3150,5780 h60
  text "Copper" at 4079.74,5780 h60
  text "1.40mil" at 4939.51,5780 h60
  text "6" at 2740.09,5660 h60
  text "Dielectric2" at 3150,5660 h60
  text "FR-4" at 4079.74,5660 h60
  text "31.00mil" at 4939.51,5660 h60
  text "4.8" at 5589.35,5660 h60
  text "7" at 2740.09,5540 h60
  text "MidLayer2" at 3150,5540 h60
  text "Copper" at 4079.74,5540 h60
  text "1.40mil" at 4939.51,5540 h60
  text "8" at 2740.09,5420 h60
  text "Dielectric3" at 3150,5420 h60
  text "FR-4" at 4079.74,5420 h60
  text "10.00mil" at 4939.51,5420 h60
  text "4.8" at 5589.35,5420 h60
  text "9" at 2740.09,5300 h60
  text "Bottom Layer" at 3150,5300 h60
  text "Copper" at 4079.74,5300 h60
  text "2.80mil" at 4939.51,5300 h60
  text "10" at 2740.09,5180 h60
  text "Bottom Solder" at 3150,5180 h60
  text "Solder Resist" at 4079.74,5180 h60
  text "0.40mil" at 4939.51,5180 h60
  text "3.5" at 5589.35,5180 h60
  text "11" at 2740.09,5060 h60
  text "Bottom Overlay" at 3150,5060 h60
  text ".Layer_Name" at -751,-1769.49 h60
M13 Component Bodies Top:
  text ".Layer_Name" at -751,-1769.49 h60
M14 Component Bodies Bottom:
  text ".Layer_Name" at -751,-1769.49 h60
M15 Courtyards Top:
  circle w7: c1325,1835 r135.83
  circle w7: c1315,205 r135.83
  circle w7: c3595,1845 r135.83
  circle w7: c3595,205 r135.83
  text ".Layer_Name" at -751,-1769.49 h60
M16 Courtyards Bottom:
  text ".Layer_Name" at -751,-1769.49 h60
Drill Drawing:
  circle w10: c2680.05,3613.33 r33.33
  lines w10: 2646.71,3730 2680.05,3746.67 2713.38,3730 2696.71,3763.33 2713.38,3796.67 2680.05,3780 2646.71,3796.67 2663.38,3763.33 2646.71,3730 ; 2646.71,3880 2713.38,3880 2713.38,3946.67 2646.71,3946.67 2646.71,3880 ; 2646.71,4096.67 2713.38,4096.67 2680.05,4030 2646.71,4096.67 ; 2646.71,4180 2646.71,4196.67 2663.38,4213.33 2646.71,4230 2646.71,4246.67 2663.38,4246.67 2680.05,4230 2696.71,4246.67 2713.38,4246.67 2713.38,4230 2696.71,4213.33 2713.38,4196.67 2713.38,4180 2696.71,4180 2680.05,4196.67 2663.38,4180 2646.71,4180 ; 2646.71,4346.67 2663.38,4346.67 2663.38,4330 2696.71,4330 2696.71,4346.67 2713.38,4346.67 2713.38,4380 2696.71,4380 2696.71,4396.67 2663.38,4396.67 2663.38,4380 2646.71,4380 2646.71,4346.67 ; 2646.71,4496.67 2663.38,4496.67 2680.05,4480 2696.71,4496.67 2713.38,4496.67 2696.71,4513.33 2713.38,4530 2696.71,4530 2680.05,4546.67 2663.38,4530 2646.71,4530 2663.38,4513.33 2646.71,4496.67
  lines w15: 2586.92,3535 9736.98,3535 ; 2586.92,4585 9736.98,4585 ; 3137.8,3385 3137.8,4735 ; 3677.66,3385 3677.66,4735 ; 4827.32,3385 4827.32,4735 ; 5333.2,3385 5333.2,4735 ; 6067,3385 6067,4735 ; 7566.55,3385 7566.55,4735 ; 8156.4,3385 8156.4,4735 ; 8902.2,3385 8902.2,4735 ; 2586.92,3385 9736.98,3385 9736.98,4735 2586.92,4735 2586.92,3385
  text "Symbol" at 2676.92,4630 h72
  text "Count" at 3182.8,4630 h72
  text "Hole Size" at 3722.66,4630 h72
  text "Plated" at 4872.32,4630 h72
  text "Hole Type" at 5378.2,4630 h72
  text "Drill Layer Pair" at 6112,4630 h72
  text "Via/Pad" at 7611.55,4630 h72
  text "Pad Shape" at 8201.4,4630 h72
  text "Template" at 8947.2,4630 h72
  text "Drill Table" at 2591,4567 h60
  text "3" at 3182.8,4480 h60
  text "98.43mil (2.500mm)" at 3722.66,4480 h60
  text "PTH" at 4872.32,4480 h60
  text "Round" at 5378.2,4480 h60
  text "Top Layer - Bottom Layer" at 6112,4480 h60
  text "Pad" at 7611.55,4480 h60
  text "Rounded" at 8201.4,4480 h60
  text "c350h250" at 8947.2,4480 h60
  text "4" at 3182.8,4330 h60
  text "137.80mil (3.500mm)" at 3722.66,4330 h60
  text "PTH" at 4872.32,4330 h60
  text "Round" at 5378.2,4330 h60
  text "Top Layer - Bottom Layer" at 6112,4330 h60
  text "Pad" at 7611.55,4330 h60
  text "Rounded" at 8201.4,4330 h60
  text "c640h350" at 8947.2,4330 h60
  text "5" at 3182.8,4180 h60
  text "28.00mil (0.711mm)" at 3722.66,4180 h60
  text "PTH" at 4872.32,4180 h60
  text "Round" at 5378.2,4180 h60
  text "Top Layer - Bottom Layer" at 6112,4180 h60
  text "Via" at 7611.55,4180 h60
  text "Rounded" at 8201.4,4180 h60
  text "v127h71m0mx0" at 8947.2,4180 h60
  text "6" at 3182.8,4030 h60
  text "12.99mil (0.330mm)" at 3722.66,4030 h60
  text "PTH" at 4872.32,4030 h60
  text "Round" at 5378.2,4030 h60
  text "Top Layer - Bottom Layer" at 6112,4030 h60
  text "Via" at 7611.55,4030 h60
  text "Rounded" at 8201.4,4030 h60
  text "v63h33m63" at 8947.2,4030 h60
  text "8" at 3182.8,3880 h60
  text "50.00mil (1.270mm)" at 3722.66,3880 h60
  text "PTH" at 4872.32,3880 h60
  text "Round" at 5378.2,3880 h60
  text "Top Layer - Bottom Layer" at 6112,3880 h60
  text "Pad" at 7611.55,3880 h60
  text "(Mixed)" at 8201.4,3880 h60
  text "(Mixed)" at 8947.2,3880 h60
  text "9" at 3182.8,3730 h60
  text "40.00mil (1.016mm)" at 3722.66,3730 h60
  text "PTH" at 4872.32,3730 h60
  text "Round" at 5378.2,3730 h60
  text "Top Layer - Bottom Layer" at 6112,3730 h60
  text "Pad" at 7611.55,3730 h60
  text "(Mixed)" at 8201.4,3730 h60
  text "(Mixed)" at 8947.2,3730 h60
  text "62" at 3182.8,3580 h60
  text "10.00mil (0.254mm)" at 3722.66,3580 h60
  text "PTH" at 4872.32,3580 h60
  text "Round" at 5378.2,3580 h60
  text "Top Layer - Bottom Layer" at 6112,3580 h60
  text "Via" at 7611.55,3580 h60
  text "Rounded" at 8201.4,3580 h60
  text "v51h25m0mx0" at 8947.2,3580 h60
  text "97 Total" at 3182.8,3430 h60
  text ".Layer_Name" at -751,-1769.49 h60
